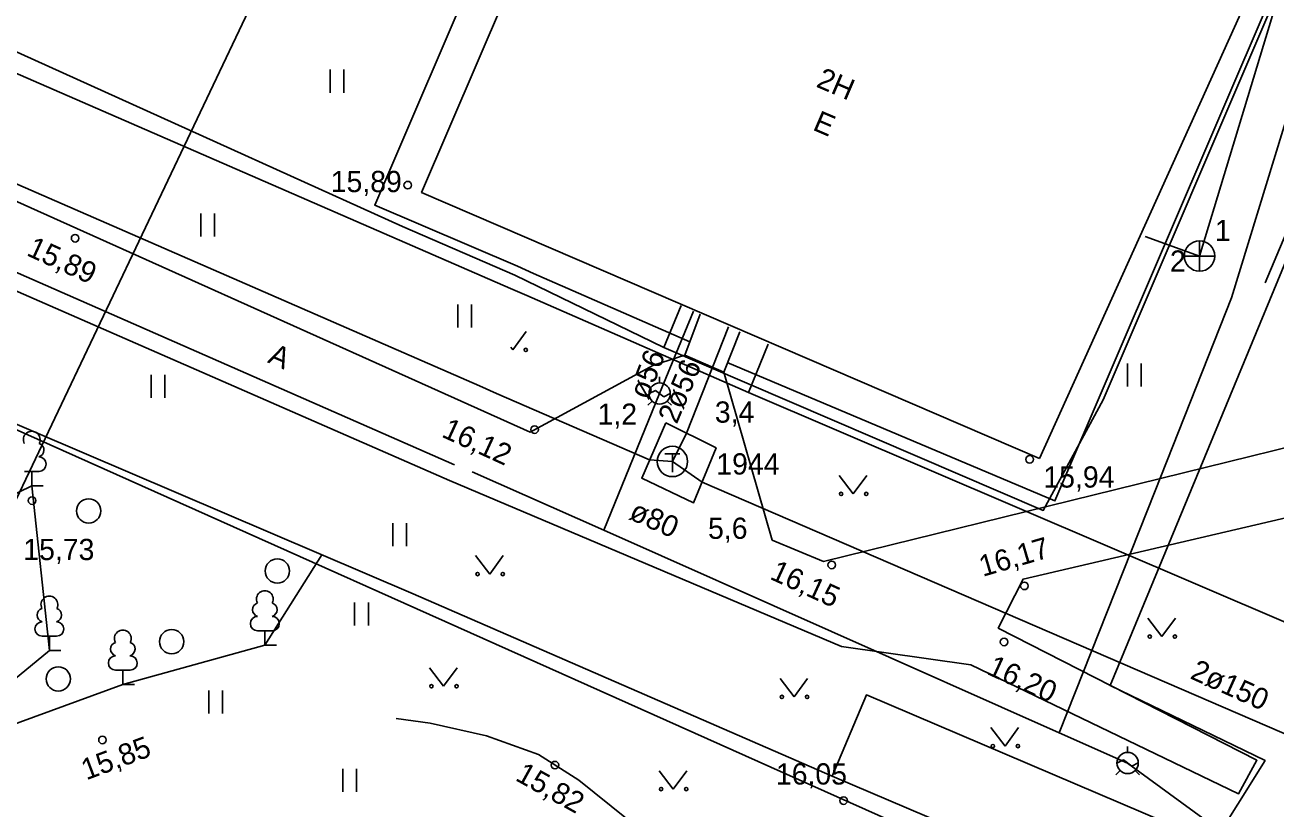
# Model space of a CAD drawing. Extents: x 713540 to 713867, y 6589774 to 6590061.
# Drawn here: x 713573.1 to 713614.29, y 6589915.75 to 6589941.56 of the extents above; entities that cross this region are included whole.
import ezdxf

# ---------------------------------------------------------------- set-up
doc = ezdxf.new("R2010")
doc.units = 0
for name, color, linetype in [('HALJASTUS', 7, 'Continuous'), ('HOONE', 7, 'Continuous'), ('HOONEDET', 7, 'Continuous'), ('KAEVU_NR', 7, 'Continuous'), ('KKAEV', 7, 'Continuous'), ('KORGUS', 7, 'Continuous'), ('KTRASS', 7, 'Continuous'), ('MPKAABEL', 7, 'Continuous'), ('PUU', 7, 'Continuous'), ('SITRASS', 7, 'Continuous'), ('TEE', 7, 'Continuous'), ('TKAEV', 7, 'Continuous'), ('TORU NR', 7, 'Continuous'), ('TTRASS', 7, 'Continuous'), ('По умолчанию', 7, 'Continuous'), ('Слой 1', 7, 'Continuous')]:
    doc.layers.add(name, color=color, linetype=linetype)

msp = doc.modelspace()

# ---------------------------------------------------------------- linework, layer by layer
at = {"layer": 'HALJASTUS'}
for p, q in [((713583.152, 6589940.089), (713583.152, 6589939.328)), ((713583.607, 6589940.089), (713583.607, 6589939.328)), ((713578.889, 6589935.348), (713578.889, 6589934.587)), ((713579.344, 6589935.348), (713579.344, 6589934.587)), ((713587.355, 6589932.348), (713587.355, 6589931.587)), ((713587.81, 6589932.348), (713587.81, 6589931.587)), ((713609.427, 6589930.401), (713609.427, 6589929.64)), ((713609.882, 6589930.401), (713609.882, 6589929.64)), ((713577.255, 6589930.03), (713577.255, 6589929.269)), ((713577.71, 6589930.03), (713577.71, 6589929.269)), ((713599.927, 6589926.707), (713600.39, 6589926.1)), ((713600.39, 6589926.1), (713600.836, 6589926.707)), ((713585.218, 6589925.135), (713585.218, 6589924.374)), ((713585.673, 6589925.135), (713585.673, 6589924.374)), ((713587.947, 6589924.067), (713588.41, 6589923.46)), ((713588.41, 6589923.46), (713588.856, 6589924.067)), ((713583.96, 6589922.522), (713583.96, 6589921.761)), ((713584.415, 6589922.522), (713584.415, 6589921.761)), ((713610.097, 6589922.007), (713610.56, 6589921.4)), ((713610.56, 6589921.4), (713611.006, 6589922.007)), ((713586.427, 6589920.367), (713586.89, 6589919.76)), ((713586.89, 6589919.76), (713587.336, 6589920.367)), ((713597.977, 6589920.017), (713598.44, 6589919.41)), ((713598.44, 6589919.41), (713598.886, 6589920.017)), ((713579.154, 6589919.621), (713579.154, 6589918.86)), ((713579.609, 6589919.621), (713579.609, 6589918.86)), ((713604.927, 6589918.397), (713605.39, 6589917.79)), ((713605.39, 6589917.79), (713605.836, 6589918.397)), ((713583.571, 6589917.04), (713583.571, 6589916.279)), ((713584.026, 6589917.04), (713584.026, 6589916.279)), ((713593.997, 6589916.977), (713594.46, 6589916.37)), ((713594.46, 6589916.37), (713594.906, 6589916.977))]:
    msp.add_line(p, q, dxfattribs=at)
for points in [[(713616.805, 6589939.809), (713613.958, 6589933.059)], [(713559.941, 6589933.731), (713559.092, 6589931.488), (713560.846, 6589927.994), (713560.732, 6589923.44), (713565.176, 6589918.555), (713567.51, 6589923.545), (713573.32, 6589926.37), (713573.9, 6589920.935), (713569.517, 6589917.336), (713576.32, 6589919.815), (713581, 6589921.113), (713582.883, 6589924.094)]]:
    msp.add_lwpolyline(points, dxfattribs=at)
for centre, radius in [((713599.989, 6589926.1), 0.055), ((713600.818, 6589926.1), 0.055), ((713575.196, 6589925.541), 0.4), ((713581.414, 6589923.561), 0.4), ((713588.009, 6589923.46), 0.055), ((713588.838, 6589923.46), 0.055), ((713577.929, 6589921.231), 0.4), ((713610.159, 6589921.4), 0.055), ((713610.988, 6589921.4), 0.055), ((713574.193, 6589920.003), 0.4), ((713586.489, 6589919.76), 0.055), ((713587.318, 6589919.76), 0.055), ((713598.039, 6589919.41), 0.055), ((713598.868, 6589919.41), 0.055), ((713604.989, 6589917.79), 0.055), ((713605.818, 6589917.79), 0.055), ((713594.059, 6589916.37), 0.055), ((713594.888, 6589916.37), 0.055)]:
    msp.add_circle(centre, radius, dxfattribs=at)
at = {"layer": 'HOONE'}
for p, q in [((713594.01, 6589929.76), (713594.01, 6589929.957)), ((713593.66, 6589929.408), (713593.871, 6589929.514)), ((713593.871, 6589929.514), (713594.149, 6589929.306)), ((713594.149, 6589929.306), (713594.36, 6589929.412)), ((713593.763, 6589929.163), (713593.623, 6589929.023)), ((713594.257, 6589929.163), (713594.397, 6589929.023)), ((713609.43, 6589917.58), (713609.43, 6589917.777)), ((713609.183, 6589916.983), (713609.043, 6589916.843)), ((713609.08, 6589917.228), (713609.291, 6589917.334)), ((713609.291, 6589917.334), (713609.569, 6589917.126)), ((713609.569, 6589917.126), (713609.78, 6589917.232)), ((713609.677, 6589916.983), (713609.817, 6589916.843))]:
    msp.add_line(p, q, dxfattribs=at)
for points in [[(713606.522, 6589927.274), (713586.167, 6589936.04), (713592.564, 6589950.969), (713613.312, 6589942.295), (713606.522, 6589927.274)], [(713545.37, 6589945.41), (713554.46, 6589941.41), (713557.306, 6589940.21), (713587.249, 6589927.065)], [(713610.336, 6589926.205), (713612.85, 6589932.56), (713616.283, 6589943.752)], [(713595.12, 6589932.13), (713594.01, 6589929.41)], [(713594.01, 6589929.41), (713592.17, 6589924.91)], [(713587.836, 6589926.832), (713592.17, 6589924.91)], [(713610.336, 6589926.205), (713607.18, 6589918.23)], [(713592.17, 6589924.91), (713607.18, 6589918.23)], [(713599.692, 6589916.794), (713600.822, 6589919.474), (713611.512, 6589914.914), (713610.312, 6589912.274), (713599.692, 6589916.794)], [(713607.18, 6589918.23), (713609.43, 6589917.22)], [(713609.43, 6589917.22), (713616.586, 6589911.996), (713631.91, 6589900.81), (713633.77, 6589899.45), (713649.493, 6589887.937), (713658.68, 6589881.21), (713662.78, 6589860.48)]]:
    msp.add_lwpolyline(points, dxfattribs=at)
for centre in [(713594.01, 6589929.41), (713609.43, 6589917.23)]:
    msp.add_circle(centre, 0.35, dxfattribs=at)
at = {"layer": 'HOONEDET'}
for points in [[(713595, 6589931.11), (713589.855, 6589933.364), (713589.331, 6589933.604), (713584.62, 6589935.623), (713591.762, 6589952.291), (713614.231, 6589942.663), (713607.035, 6589925.868), (713596.24, 6589930.43)], [(713596.65, 6589931.45), (713596.12, 6589930.12), (713594.84, 6589930.68), (713595.35, 6589932.03)]]:
    msp.add_lwpolyline(points, dxfattribs=at)
at = {"layer": 'KKAEV'}
for p, q in [((713611.8, 6589933.443), (713611.8, 6589934.443)), ((713611.3, 6589933.943), (713612.3, 6589933.943))]:
    msp.add_line(p, q, dxfattribs=at)
msp.add_circle((713611.8, 6589933.943), 0.5, dxfattribs=at)
at = {"layer": 'KORGUS'}
for centre in [(713585.71, 6589936.28), (713574.75, 6589934.53), (713589.89, 6589928.22), (713606.2, 6589927.24), (713573.33, 6589925.88), (713599.68, 6589923.76), (713606.03, 6589923.07), (713605.36, 6589921.22), (713575.65, 6589917.99), (713590.56, 6589917.16), (713600.07, 6589915.99)]:
    msp.add_circle(centre, 0.125, dxfattribs=at)
at = {"layer": 'KTRASS'}
for p, q in [((713618.35, 6589955.601), (713611.8, 6589933.943)), ((713582.594, 6589946.514), (713571.452, 6589923.075)), ((713611.8, 6589933.943), (713610.01, 6589934.589))]:
    msp.add_line(p, q, dxfattribs=at)
at = {"layer": 'MPKAABEL'}
for points in [[(713626.354, 6589990.991), (713626.025, 6589988.675), (713621.796, 6589978.429), (713617.679, 6589969.517), (713616.38, 6589965.95), (713614.069, 6589960.385), (713612.538, 6589956.831), (713611.255, 6589953.855), (713609.284, 6589948.917), (713608.569, 6589945.656), (713614.381, 6589942.657), (713608.627, 6589929.201), (713606.65, 6589925.56), (713594.15, 6589930.93)], [(713594.15, 6589930.93), (713589.237, 6589933.309), (713585.538, 6589934.915), (713565.904, 6589943.804), (713562.25, 6589945.144), (713558.411, 6589946.766), (713543.01, 6589953.59)], [(713594.72, 6589932.31), (713594.15, 6589930.93)]]:
    msp.add_lwpolyline(points, dxfattribs=at)
at = {"layer": 'PUU'}
for p, q in [((713573.56, 6589926.845), (713573.08, 6589926.845)), ((713573.32, 6589926.37), (713573.32, 6589926.845)), ((713573.7, 6589926.37), (713573.32, 6589926.37)), ((713581.24, 6589921.588), (713580.76, 6589921.588)), ((713581, 6589921.113), (713581, 6589921.588)), ((713574.14, 6589921.41), (713573.66, 6589921.41)), ((713573.9, 6589920.935), (713573.9, 6589921.41)), ((713581.38, 6589921.113), (713581, 6589921.113)), ((713574.28, 6589920.935), (713573.9, 6589920.935)), ((713576.56, 6589920.29), (713576.08, 6589920.29)), ((713576.32, 6589919.815), (713576.32, 6589920.29)), ((713576.7, 6589919.815), (713576.32, 6589919.815))]:
    msp.add_line(p, q, dxfattribs=at)
for centre, radius, start, end in [((713573.32, 6589927.89), 0.277, 332.5799, 207.4201), ((713573.49, 6589927.543), 0.233, 286.8508, 70.9859), ((713573.557, 6589927.082), 0.238, 270.6047, 89.9984), ((713573.9, 6589922.455), 0.277, 332.5799, 207.4201), ((713581, 6589922.633), 0.277, 332.5799, 207.4201), ((713573.73, 6589922.108), 0.233, 109.0217, 253.1415), ((713574.07, 6589922.108), 0.233, 286.8508, 70.9859), ((713580.83, 6589922.285), 0.233, 109.0217, 253.1415), ((713581.171, 6589922.285), 0.233, 286.8508, 70.9859), ((713573.663, 6589921.647), 0.238, 90.0016, 269.3953), ((713574.137, 6589921.647), 0.238, 270.6047, 89.9984), ((713580.763, 6589921.825), 0.238, 90.0016, 269.3953), ((713581.238, 6589921.825), 0.238, 270.6047, 89.9984), ((713576.32, 6589921.335), 0.277, 332.5799, 207.4201), ((713576.15, 6589920.988), 0.233, 109.0217, 253.1415), ((713576.49, 6589920.988), 0.233, 286.8508, 70.9859), ((713576.083, 6589920.527), 0.238, 90.0016, 269.3953), ((713576.557, 6589920.527), 0.238, 270.6047, 89.9984)]:
    msp.add_arc(centre, radius, start, end, dxfattribs=at)
at = {"layer": 'SITRASS'}
for points in [[(713680.76, 6589850.01), (713672.23, 6589848.51), (713669.283, 6589865.987), (713667.62, 6589875.84), (713665.21, 6589875.309), (713665.174, 6589875.301), (713663.67, 6589874.97), (713661.62, 6589885.51), (713653.61, 6589896.45), (713649.76, 6589901.81), (713649.429, 6589901.945), (713648.305, 6589902.402), (713638.16, 6589906.53), (713639.91, 6589911.24), (713638.2, 6589911.92), (713614.722, 6589921.827), (713596.94, 6589929.45), (713589.631, 6589932.637), (713589.097, 6589932.87), (713558.329, 6589946.285), (713549.9, 6589949.96), (713539.965, 6589954.262)], [(713597.59, 6589931.04), (713596.94, 6589929.45)]]:
    msp.add_lwpolyline(points, dxfattribs=at)
at = {"layer": 'TEE'}
for points in [[(713574.899, 6589963.436), (713570.809, 6589952.474), (713564.568, 6589941.113), (713564.397, 6589939.89), (713565.674, 6589938.592), (713569.486, 6589937.234), (713589.739, 6589928.138), (713593.81, 6589930.35), (713594.84, 6589930.68)], [(713574.899, 6589963.436), (713590.337, 6589957.176), (713603.764, 6589951.419), (713623.637, 6589942.963), (713642.688, 6589934.75), (713628.305, 6589930.999), (713599.405, 6589923.875), (713597.72, 6589924.58), (713596.12, 6589930.12)], [(713672.463, 6589922.262), (713648.565, 6589932.421), (713645.27, 6589932.41), (713628.521, 6589928.56), (713605.988, 6589923.296), (713605.17, 6589921.68), (713613.69, 6589917.32), (713613.08, 6589916.21), (713604.26, 6589920.47), (713600, 6589921.07), (713587.083, 6589926.544), (713569.619, 6589934.182), (713565.934, 6589935.405), (713565.316, 6589935.654), (713563.338, 6589936.228), (713561.999, 6589936.133), (713560.468, 6589935.495), (713559.188, 6589934.236), (713557.045, 6589923.518), (713553.905, 6589910.439)], [(713559.413, 6589934.126), (713585.893, 6589922.808), (713599.692, 6589916.794)], [(713585.323, 6589918.701), (713586.45, 6589918.54), (713588.3, 6589918.13), (713590.02, 6589917.51), (713591.35, 6589916.66), (713592.92, 6589915.4)]]:
    msp.add_lwpolyline(points, dxfattribs=at)
at = {"layer": 'TKAEV'}
for p, q in [((713594.18, 6589927.42), (713594.68, 6589927.42)), ((713594.43, 6589926.82), (713594.43, 6589927.42))]:
    msp.add_line(p, q, dxfattribs=at)
msp.add_circle((713594.43, 6589927.17), 0.5, dxfattribs=at)
at = {"layer": 'TTRASS'}
for points in [[(713565.972, 6589939.303), (713588.076, 6589929.662), (713588.634, 6589929.411), (713593.68, 6589927.22), (713594.43, 6589927.17)], [(713596.28, 6589931.61), (713594.89, 6589928.1), (713594.43, 6589927.17)], [(713594.21, 6589928.44), (713593.42, 6589926.62), (713595.13, 6589925.81), (713595.87, 6589927.62), (713594.21, 6589928.44)], [(713594.43, 6589927.17), (713595.41, 6589926.49), (713615.482, 6589917.82), (713621.5, 6589915.22)]]:
    msp.add_lwpolyline(points, dxfattribs=at)
at = {"layer": 'По умолчанию'}
for p, q in [((713589.17, 6589930.85), (713589.616, 6589931.457)), ((713589.105, 6589930.935), (713589.17, 6589930.85))]:
    msp.add_line(p, q, dxfattribs=at)
msp.add_circle((713589.598, 6589930.85), 0.055, dxfattribs=at)
at = {"layer": 'Слой 1'}
msp.add_lwpolyline([(713573.6, 6589964.85), (713619.06, 6589944.46), (713608.85, 6589919.78), (713613.96, 6589917.31), (713610.41, 6589911.64), (713607.67, 6589912.62), (713560.07, 6589933.92)], close=True, dxfattribs=at)

# ---------------------------------------------------------------- texts
at = {"layer": 'HOONE'}
for s, p in [('2H', (713599.135, 6589939.535)), ('E', (713599.02, 6589938.115))]:
    msp.add_text(s, height=0.7, rotation=336.8053, dxfattribs=at).set_placement(p)
at = {"layer": 'KAEVU_NR'}
msp.add_text('1944', height=0.7, dxfattribs=at).set_placement((713595.877, 6589926.74))
at = {"layer": 'KORGUS'}
for s, p in [('15,89', (713583.172, 6589936.05)), ('15,94', (713606.654, 6589926.31)), ('15,73', (713573.041, 6589923.92)), ('16,05', (713597.841, 6589916.52))]:
    msp.add_text(s, height=0.7, dxfattribs=at).set_placement(p)
for s, rotation, p in [('15,89', 335.3843, (713573.116, 6589933.979)), ('16,12', 335.3843, (713586.793, 6589927.997)), ('16,17', 16.2988, (713604.658, 6589923.365)), ('16,15', 335.3843, (713597.607, 6589923.311)), ('16,20', 335.3843, (713604.76, 6589920.176)), ('15,85', 20.6079, (713575.116, 6589916.655)), ('15,82', 331.0097, (713589.22, 6589916.678))]:
    msp.add_text(s, height=0.7, rotation=rotation, dxfattribs=at).set_placement(p)
at = {"layer": 'TEE'}
msp.add_text('A', height=0.7, rotation=336.4588, dxfattribs=at).set_placement((713581.064, 6589930.444))
at = {"layer": 'TORU NR'}
for s, p in [('1', (713612.305, 6589934.436)), ('2', (713610.824, 6589933.428)), ('1,2', (713591.964, 6589928.38)), ('3,4', (713595.829, 6589928.45)), ('5,6', (713595.604, 6589924.62))]:
    msp.add_text(s, height=0.7, dxfattribs=at).set_placement(p)
for s, rotation, p in [('ø56', 68.9625, (713593.624, 6589929.173)), ('2ø56', 67.2856, (713594.574, 6589928.376)), ('ø80', 335.8978, (713592.96, 6589925.289)), ('2ø150', 335.7941, (713611.455, 6589920.032))]:
    msp.add_text(s, height=0.7, rotation=rotation, dxfattribs=at).set_placement(p)

doc.saveas('drawing.dxf')
